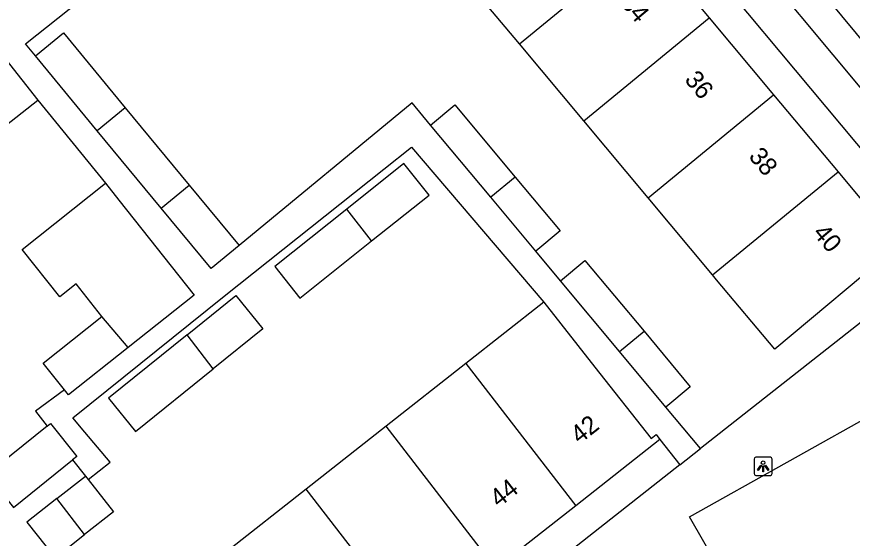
# Model space of a CAD drawing. Extents: x 160379 to 161131, y 383940 to 384849.
# Drawn here: x 160797.2 to 160843.25, y 384370.35 to 384399.1 of the extents above; entities that cross this region are included whole.
import ezdxf

# ---------------------------------------------------------------- set-up
doc = ezdxf.new("R2010")
doc.units = 0
for name, color, linetype in [('IMGEO_Lichtpunt', 7, 'Continuous'), ('IMGEO_Pand', 7, 'Continuous'), ('IMGEO_Pand_nummerreeks', 7, 'Continuous'), ('IMGEO_Rijbaan_lokaal_open', 7, 'Continuous'), ('IMGEO_Voetpad_open', 7, 'Continuous')]:
    doc.layers.add(name, color=color, linetype=linetype)

msp = doc.modelspace()

# ---------------------------------------------------------------- linework, layer by layer
at = {"layer": 'IMGEO_Lichtpunt'}
for p, q in [((160837.839, 384374.719), (160837.839, 384373.912)), ((160837.839, 384374.719), (160837.839, 384373.912)), ((160838.741, 384374.814), (160837.933, 384374.814)), ((160838.741, 384374.814), (160837.933, 384374.814)), ((160838.835, 384373.912), (160838.835, 384374.719)), ((160838.835, 384373.912), (160838.835, 384374.719)), ((160837.933, 384373.818), (160838.741, 384373.818)), ((160837.933, 384373.818), (160838.741, 384373.818))]:
    msp.add_line(p, q, dxfattribs=at)
for points in [[(160838.213, 384374.383), (160838.252, 384374.355), (160838.064, 384374.093), (160838.026, 384374.12), (160838.213, 384374.383)], [(160838.315, 384374.335), (160838.362, 384374.335), (160838.362, 384374.013), (160838.315, 384374.013), (160838.315, 384374.335)], [(160838.425, 384374.355), (160838.463, 384374.382), (160838.65, 384374.12), (160838.611, 384374.092), (160838.425, 384374.355)]]:
    msp.add_lwpolyline(points, dxfattribs=at)
msp.add_circle((160838.338, 384374.517), 0.0994, dxfattribs=at)
for centre, start, end in [((160837.933, 384374.719), 90, 180), ((160837.933, 384374.719), 90, 180), ((160838.741, 384374.719), 0, 90), ((160838.741, 384374.719), 0, 90), ((160837.933, 384373.912), 180, 270), ((160837.933, 384373.912), 180, 270), ((160838.741, 384373.912), 270, 0), ((160838.741, 384373.912), 270, 360)]:
    msp.add_arc(centre, 0.0946, start, end, dxfattribs=at)
at = {"layer": 'IMGEO_Pand'}
for points in [[(160824.902, 384397.608), (160831.815, 384403.291)], [(160831.815, 384403.291), (160835.366, 384399.044)], [(160824.902, 384397.608), (160821.351, 384401.855)], [(160828.453, 384393.361), (160835.366, 384399.044)], [(160835.366, 384399.044), (160838.917, 384394.797)], [(160798.235, 384396.937), (160799.777, 384398.211), (160803.183, 384394.086)], [(160828.453, 384393.361), (160824.902, 384397.608)], [(160801.638, 384392.816), (160798.235, 384396.937)], [(160791.821, 384392.991), (160796.594, 384396.738), (160798.357, 384394.492)], [(160791.821, 384392.991), (160793.584, 384390.745), (160798.357, 384394.492)], [(160832.004, 384389.114), (160838.917, 384394.797)], [(160838.917, 384394.797), (160842.469, 384390.55)], [(160803.183, 384394.086), (160801.638, 384392.816)], [(160803.183, 384394.086), (160806.708, 384389.818)], [(160820.009, 384393.125), (160821.353, 384394.246), (160824.68, 384390.259)], [(160823.328, 384389.148), (160820.009, 384393.125)], [(160832.004, 384389.114), (160828.453, 384393.361)], [(160805.163, 384388.548), (160801.638, 384392.816)], [(160816.747, 384386.739), (160819.922, 384389.272), (160818.535, 384391.011), (160815.388, 384388.5)], [(160842.469, 384390.55), (160845.844, 384386.514), (160838.987, 384380.767), (160835.777, 384384.602), (160835.555, 384384.867)], [(160835.555, 384384.867), (160842.469, 384390.55)], [(160801.894, 384382.58), (160800.468, 384384.376), (160799.565, 384383.659), (160797.493, 384386.269), (160802.089, 384389.918)], [(160802.089, 384389.918), (160802.834, 384388.98), (160806.983, 384383.754), (160803.343, 384380.864)], [(160824.68, 384390.259), (160823.328, 384389.148)], [(160824.68, 384390.259), (160827.158, 384387.29), (160825.814, 384386.169)], [(160805.163, 384388.548), (160806.708, 384389.818)], [(160806.708, 384389.818), (160809.46, 384386.487)], [(160825.814, 384386.169), (160823.328, 384389.148)], [(160835.555, 384384.867), (160832.004, 384389.114)], [(160809.46, 384386.487), (160807.917, 384385.213), (160805.163, 384388.548)], [(160815.388, 384388.5), (160811.416, 384385.33), (160812.804, 384383.591), (160816.747, 384386.739)], [(160816.747, 384386.739), (160815.388, 384388.5)], [(160827.166, 384384.549), (160828.51, 384385.67), (160831.774, 384381.759)], [(160830.422, 384380.648), (160827.166, 384384.549)], [(160806.594, 384381.564), (160809.278, 384383.728), (160810.758, 384381.893), (160808.034, 384379.697)], [(160826.254, 384383.371), (160821.956, 384379.988)], [(160826.254, 384383.371), (160829.071, 384379.787), (160832.16, 384375.855), (160832.435, 384376.071), (160832.651, 384375.795)], [(160799.835, 384378.531), (160798.659, 384380.011), (160801.894, 384382.58)], [(160803.343, 384380.864), (160801.894, 384382.58)], [(160806.594, 384381.564), (160802.258, 384378.068), (160803.737, 384376.234), (160808.034, 384379.697)], [(160808.034, 384379.697), (160806.594, 384381.564)], [(160830.422, 384380.648), (160831.774, 384381.759)], [(160831.774, 384381.759), (160834.321, 384378.707), (160832.977, 384377.585)], [(160803.343, 384380.864), (160800.055, 384378.253), (160799.835, 384378.531)], [(160832.977, 384377.585), (160830.422, 384380.648)], [(160821.956, 384379.988), (160817.555, 384376.524)], [(160821.956, 384379.988), (160828.01, 384372.142)], [(160798.879, 384376.535), (160795.555, 384373.87), (160797.014, 384372.05), (160800.279, 384374.669)], [(160798.879, 384376.535), (160799.053, 384376.675), (160800.512, 384374.856), (160800.279, 384374.669)], [(160817.555, 384376.524), (160813.155, 384373.06)], [(160823.609, 384368.678), (160817.555, 384376.524)], [(160832.651, 384375.795), (160828.01, 384372.142)], [(160799.413, 384372.536), (160800.993, 384373.778)], [(160800.993, 384373.778), (160801.133, 384373.599)], [(160801.133, 384373.599), (160802.537, 384371.813), (160800.939, 384370.558)], [(160813.155, 384373.06), (160808.754, 384369.597)], [(160819.208, 384365.214), (160813.155, 384373.06)], [(160799.413, 384372.536), (160797.763, 384371.239), (160799.307, 384369.274), (160800.939, 384370.558)], [(160800.939, 384370.558), (160799.413, 384372.536)], [(160828.01, 384372.142), (160823.609, 384368.678)]]:
    msp.add_lwpolyline(points, dxfattribs=at)
at = {"layer": 'IMGEO_Rijbaan_lokaal_open'}
msp.add_lwpolyline([(160848.692, 384391.913), (160839.724, 384402.734), (160826.616, 384418.342), (160812.279, 384435.487), (160810.072, 384438.161)], dxfattribs=at)
at = {"layer": 'IMGEO_Voetpad_open'}
for points in [[(160807.803, 384434.788), (160848.557, 384386.056)], [(160798.235, 384396.937), (160797.689, 384397.598), (160809.626, 384407.111), (160806.851, 384410.429)], [(160845.81, 384392.668), (160838.586, 384401.357)], [(160798.357, 384394.492), (160802.089, 384389.918)], [(160820.009, 384393.125), (160818.986, 384394.352), (160809.46, 384386.487)], [(160801.133, 384373.599), (160802.345, 384374.551), (160800.957, 384376.191), (160800.288, 384376.981), (160808.637, 384383.688), (160817.426, 384390.696), (160818.954, 384391.914), (160826.254, 384383.371)], [(160827.166, 384384.549), (160825.814, 384386.169)], [(160848.557, 384386.056), (160834.888, 384375.294)], [(160799.835, 384378.531), (160798.225, 384377.35), (160798.879, 384376.535)], [(160834.888, 384375.294), (160832.977, 384377.585)], [(160835.853, 384368.774), (160834.276, 384371.524), (160845.052, 384377.566), (160847.194, 384373.694)], [(160832.651, 384375.795), (160833.751, 384374.399)], [(160833.751, 384374.399), (160834.888, 384375.294)], [(160800.279, 384374.669), (160800.993, 384373.778)], [(160833.751, 384374.399), (160805.632, 384352.26), (160804.464, 384351.34)]]:
    msp.add_lwpolyline(points, dxfattribs=at)

# ---------------------------------------------------------------- texts
at = {"layer": 'IMGEO_Pand_nummerreeks'}
for s, rotation, p in [('34', 309.904, (160830.429, 384399.834)), ('36', 309.904, (160833.963, 384395.608)), ('38', 309.904, (160837.499, 384391.38)), ('40', 309.904, (160841.032, 384387.155)), ('42', 38.2059, (160828.216, 384375.512)), ('44', 38.2059, (160823.769, 384372.011))]:
    msp.add_text(s, height=1, rotation=rotation, dxfattribs=at).set_placement(p)

doc.saveas('drawing.dxf')
